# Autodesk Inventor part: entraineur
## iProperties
Created: 2011-09
Part Number: entraineur
Document SubType Name: Modeling
Designer: A
Manufacturer: Standard
Standards Organization: Custom
Author: A
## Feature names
1. Extrusion1
2. Extrusion2
3. Perçage1 [Hole]
4. Perçage2 [Hole]
5. Perçage3 [Hole]
